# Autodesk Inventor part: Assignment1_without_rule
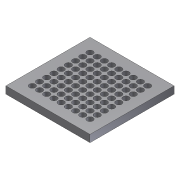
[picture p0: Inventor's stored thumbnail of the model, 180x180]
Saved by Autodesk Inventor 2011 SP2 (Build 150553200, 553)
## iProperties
Created: 2011-07
Part Number: Assignment1_without_rule
Document SubType Name: Modeling
Designer: asr06799
Density: 1 g/cm^3
Author: asr06799
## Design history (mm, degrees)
sketch "Sketch1"
  geometry: L1 (0, 0)-(700, 0); L2 (700, 0)-(700, -700); L3 (700, -700)-(0, -700); L4 (0, -700)-(0, 0)
  constraints: 8 end point, 2 parallel, 1 horizontal, 1 perpendicular
  dimensions: "d0" = 700 distance of L2.end L3.end; "d1" = 700 distance of L3.end L1.start
extrude "Plate" new body sketch "Sketch1" distance "d2" = 60; taper "d3" = 0 deg
hole "Hole1" diameter "d4" = 50; stored, may be unused: countersink angle "d13" = 90 deg, drill point angle "d15" = 118 deg; dims "d5" = 110 (computed from d8, d7, d1), "d6" = 110 (computed from d10, d9, d0), "d11" = 4, "d12" = 2, "d14" = 8, "d24" = 6
body "Solid1"
pattern_linear "Rectangular Pattern1" dims "d8" = 60
